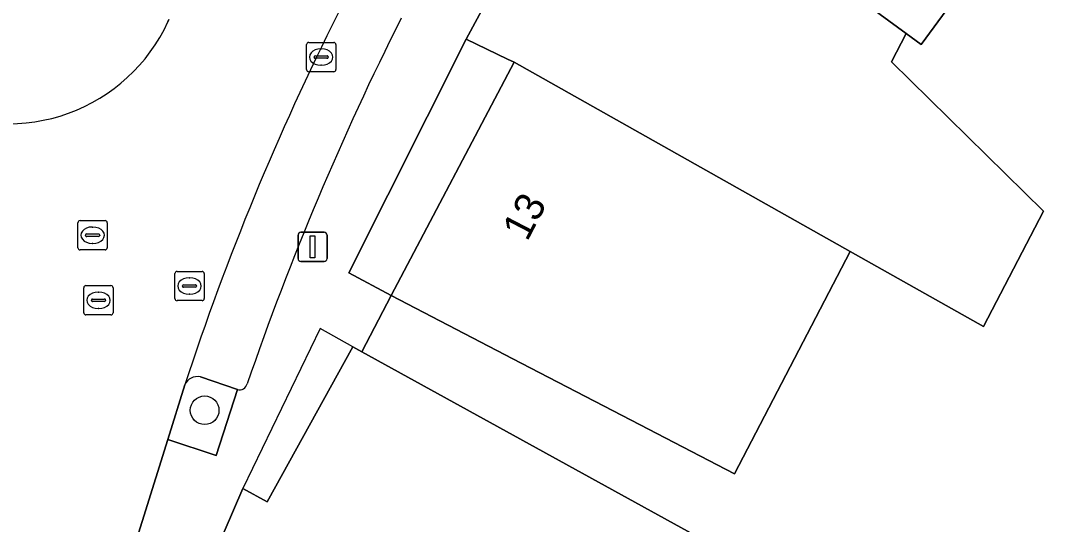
# Model space of a CAD drawing. Extents: x 159716 to 160783, y 383290 to 384031.
# Drawn here: x 160307.9 to 160343.28, y 383382.39 to 383399.58 of the extents above; entities that cross this region are included whole.
import ezdxf

# ---------------------------------------------------------------- set-up
doc = ezdxf.new("R2010")
doc.units = 0
for name, color, linetype in [('IMGEO_Boom', 7, 'Continuous'), ('IMGEO_Erf', 7, 'Continuous'), ('IMGEO_Groenvoorziening', 7, 'Continuous'), ('IMGEO_Kolk', 7, 'Continuous'), ('IMGEO_Lichtmast', 7, 'Continuous'), ('IMGEO_Pand', 7, 'Continuous'), ('IMGEO_Pand_nummerreeks', 7, 'Continuous'), ('IMGEO_Pand_overbouw', 7, 'Continuous'), ('IMGEO_Parkeervlak_open', 7, 'Continuous'), ('IMGEO_Rijbaan_lokaal_open', 7, 'Continuous'), ('IMGEO_Rioolput', 7, 'Continuous'), ('IMGEO_Voetpad_open', 7, 'Continuous')]:
    doc.layers.add(name, color=color, linetype=linetype)

msp = doc.modelspace()

# ---------------------------------------------------------------- linework, layer by layer
at = {"layer": 'IMGEO_Boom'}
msp.add_circle((160314.173, 383386.284), 0.489, dxfattribs=at)
at = {"layer": 'IMGEO_Erf'}
msp.add_lwpolyline([(160376.083, 383439.317), (160367.001, 383435.99), (160347.581, 383428.877), (160344.764, 383427.86), (160344.049, 383427.352), (160344.251, 383427.204), (160336.818, 383418.367), (160346.422, 383411.138), (160340.697, 383403.383), (160341.888, 383402.504), (160340.067, 383400.763), (160338.614, 383398.763), (160338.095, 383399.139), (160337.597, 383398.179), (160342.776, 383393.075), (160340.737, 383389.144), (160336.183, 383391.701), (160332.248, 383384.118), (160328.724, 383385.946), (160324.97, 383387.895), (160320.531, 383390.197), (160319.536, 383388.281), (160332.763, 383380.989)], dxfattribs=at)
msp.add_lwpolyline([(160324.727, 383398.163), (160324.502, 383398.272), (160323.097, 383398.955), (160319.089, 383390.972), (160320.531, 383390.197)], close=True, dxfattribs=at)
at = {"layer": 'IMGEO_Groenvoorziening'}
for points in [[(160313.497, 383387.15), (160312.912, 383385.292), (160314.565, 383384.735), (160315.29, 383386.995)], [(160315.29, 383386.995), (160314.029, 383387.421)]]:
    msp.add_lwpolyline(points, dxfattribs=at)
msp.add_arc((160313.92, 383386.977), 0.457, 76.1861, 157.8024, dxfattribs=at)
at = {"layer": 'IMGEO_Kolk'}
for p, q in [((160317.648, 383397.913), (160317.648, 383398.765)), ((160317.723, 383398.839), (160318.575, 383398.839)), ((160318.649, 383398.765), (160318.649, 383397.913)), ((160318.136, 383398.619), (160318.161, 383398.619)), ((160317.907, 383398.333), (160317.907, 383398.345)), ((160318.345, 383398.296), (160317.947, 383398.296)), ((160317.95, 383398.382), (160318.348, 383398.382)), ((160318.159, 383398.059), (160318.134, 383398.059)), ((160318.391, 383398.345), (160318.391, 383398.333)), ((160318.575, 383397.839), (160317.723, 383397.839))]:
    msp.add_line(p, q, dxfattribs=at)
for points in [[(160317.648, 383397.913), (160317.648, 383398.765)], [(160317.723, 383398.839), (160318.575, 383398.839)], [(160318.649, 383398.765), (160318.649, 383397.913)], [(160318.575, 383397.839), (160317.723, 383397.839)]]:
    msp.add_lwpolyline(points, dxfattribs=at)
for centre, radius, start, end in [((160317.725, 383398.763), 0.0765, 91.552, 178.448), ((160317.725, 383398.763), 0.0765, 91.552, 178.448), ((160318.573, 383398.763), 0.0765, 1.552, 88.448), ((160318.573, 383398.763), 0.0765, 1.552, 88.448), ((160317.947, 383398.342), 0.0403, 85.8775, 175.7526), ((160317.944, 383398.332), 0.0366, 178.938, 274.7102), ((160318.348, 383398.339), 0.043, 264.8664, 352.4533), ((160318.352, 383398.344), 0.0386, 1.7309, 96.639), ((160317.725, 383397.915), 0.0765, 181.552, 268.448), ((160317.725, 383397.915), 0.0765, 181.552, 268.448), ((160318.573, 383397.915), 0.0765, 271.552, 358.448), ((160318.573, 383397.915), 0.0765, 271.552, 358.448)]:
    msp.add_arc(centre, radius, start, end, dxfattribs=at)
for centre, major_axis, ratio, start_param, end_param in [((160318.135, 383398.339), (-0.387, 0.002), 0.722429, 4.712389, 7.853982), ((160318.16, 383398.339), (-0.39, 0.002), 0.717154, 1.570796, 4.712389)]:
    msp.add_ellipse(centre, major_axis=major_axis, ratio=ratio, start_param=start_param, end_param=end_param, dxfattribs=at)
at = {"layer": 'IMGEO_Lichtmast'}
for p, q in [((160317.357, 383391.461), (160317.357, 383392.261)), ((160317.357, 383392.261), (160317.357, 383391.461)), ((160317.457, 383392.361), (160318.247, 383392.361)), ((160318.247, 383392.361), (160317.457, 383392.361)), ((160318.347, 383392.261), (160318.347, 383391.461)), ((160318.347, 383391.461), (160318.347, 383392.261)), ((160318.247, 383391.361), (160317.457, 383391.361)), ((160317.457, 383391.361), (160318.247, 383391.361))]:
    msp.add_line(p, q, dxfattribs=at)
msp.add_lwpolyline([(160317.777, 383392.236), (160317.927, 383392.236), (160317.927, 383391.486), (160317.777, 383391.486), (160317.777, 383392.236)], dxfattribs=at)
for centre, start, end in [((160317.457, 383392.261), 90, 180), ((160317.457, 383392.261), 90, 180), ((160318.247, 383392.261), 0, 90), ((160318.247, 383392.261), 360, 90), ((160317.457, 383391.461), 180, 270), ((160317.457, 383391.461), 180, 270), ((160318.247, 383391.461), 270, 0), ((160318.247, 383391.461), 270, 0)]:
    msp.add_arc(centre, 0.1, start, end, dxfattribs=at)
at = {"layer": 'IMGEO_Pand'}
for points in [[(160346.422, 383411.138), (160336.818, 383418.367), (160336.495, 383418.61), (160327.755, 383406.719), (160338.095, 383399.139), (160338.614, 383398.763), (160340.067, 383400.763), (160341.888, 383402.504), (160340.697, 383403.383)], [(160337.597, 383398.179), (160338.095, 383399.139), (160327.755, 383406.719), (160327.556, 383406.448), (160327.951, 383406.158), (160326.397, 383404.048), (160325.966, 383404.28), (160323.097, 383398.955), (160324.502, 383398.272), (160324.727, 383398.163), (160336.183, 383391.701), (160340.737, 383389.144), (160342.776, 383393.075)], [(160336.183, 383391.701), (160324.727, 383398.163), (160320.531, 383390.197), (160324.97, 383387.895), (160328.724, 383385.946), (160332.248, 383384.118)], [(160319.536, 383388.281), (160319.229, 383388.45), (160316.304, 383383.157), (160315.48, 383383.61), (160311.554, 383374.506), (160311.589, 383373.702), (160314.742, 383371.969), (160312.038, 383367.09), (160312.191, 383364.819), (160320.956, 383359.966), (160323.258, 383367.115), (160328.865, 383370.206), (160331.054, 383372.22), (160330.864, 383372.324), (160328.643, 383373.555), (160332.763, 383380.989)]]:
    msp.add_lwpolyline(points, close=True, dxfattribs=at)
at = {"layer": 'IMGEO_Pand_overbouw'}
msp.add_lwpolyline([(160319.229, 383388.45), (160318.108, 383389.071), (160315.48, 383383.61), (160316.304, 383383.157)], close=True, dxfattribs=at)
at = {"layer": 'IMGEO_Parkeervlak_open'}
msp.add_lwpolyline([(160314.029, 383387.421), (160315.29, 383386.995)], dxfattribs=at)
for centre, radius, start, end in [((160400.482, 383358.736), 91.508, 153.31144, 161.91012), ((160410.195, 383354.715), 99.991, 153.28158, 161.04988), ((160313.92, 383386.977), 0.457, 76.1861, 157.8024), ((160315.366, 383387.247), 0.263, 253.1284, 346.8051)]:
    msp.add_arc(centre, radius, start, end, dxfattribs=at)
at = {"layer": 'IMGEO_Rijbaan_lokaal_open'}
for points in [[(160312.955, 383399.617), (160312.922, 383399.536)], [(160310.416, 383377.156), (160311.627, 383381.183), (160312.912, 383385.292), (160313.497, 383387.15)]]:
    msp.add_lwpolyline(points, dxfattribs=at)
for centre, radius, start, end in [((160400.482, 383358.736), 91.508, 153.31144, 161.91012), ((160307.473, 383402.067), 6.008, 244.9277, 335.0857)]:
    msp.add_arc(centre, radius, start, end, dxfattribs=at)
at = {"layer": 'IMGEO_Rioolput'}
for p, q in [((160309.926, 383392.758), (160310.778, 383392.758)), ((160309.851, 383391.832), (160309.851, 383392.684)), ((160310.339, 383392.538), (160310.364, 383392.538)), ((160310.852, 383392.684), (160310.852, 383391.832)), ((160310.11, 383392.252), (160310.11, 383392.264)), ((160310.548, 383392.215), (160310.15, 383392.215)), ((160310.153, 383392.301), (160310.551, 383392.301)), ((160310.594, 383392.264), (160310.594, 383392.252)), ((160310.778, 383391.758), (160309.926, 383391.758)), ((160310.362, 383391.978), (160310.337, 383391.978)), ((160313.231, 383391.025), (160314.083, 383391.025)), ((160313.156, 383390.099), (160313.156, 383390.951)), ((160313.644, 383390.805), (160313.669, 383390.805)), ((160314.157, 383390.951), (160314.157, 383390.099)), ((160310.051, 383389.612), (160310.051, 383390.464)), ((160310.126, 383390.538), (160310.978, 383390.538)), ((160310.539, 383390.318), (160310.564, 383390.318)), ((160311.052, 383390.464), (160311.052, 383389.612)), ((160313.415, 383390.519), (160313.415, 383390.531)), ((160313.853, 383390.482), (160313.455, 383390.482)), ((160313.458, 383390.568), (160313.856, 383390.568)), ((160313.899, 383390.531), (160313.899, 383390.519)), ((160310.31, 383390.032), (160310.31, 383390.044)), ((160310.748, 383389.995), (160310.35, 383389.995)), ((160310.353, 383390.081), (160310.751, 383390.081)), ((160310.794, 383390.044), (160310.794, 383390.032)), ((160314.083, 383390.025), (160313.231, 383390.025)), ((160313.667, 383390.245), (160313.642, 383390.245)), ((160310.562, 383389.758), (160310.537, 383389.758)), ((160310.978, 383389.538), (160310.126, 383389.538))]:
    msp.add_line(p, q, dxfattribs=at)
for points in [[(160309.926, 383392.758), (160310.778, 383392.758)], [(160309.851, 383391.832), (160309.851, 383392.684)], [(160310.852, 383392.684), (160310.852, 383391.832)], [(160310.778, 383391.758), (160309.926, 383391.758)], [(160313.231, 383391.025), (160314.083, 383391.025)], [(160313.156, 383390.099), (160313.156, 383390.951)], [(160314.157, 383390.951), (160314.157, 383390.099)], [(160310.051, 383389.612), (160310.051, 383390.464)], [(160310.126, 383390.538), (160310.978, 383390.538)], [(160311.052, 383390.464), (160311.052, 383389.612)], [(160314.083, 383390.025), (160313.231, 383390.025)], [(160310.978, 383389.538), (160310.126, 383389.538)]]:
    msp.add_lwpolyline(points, dxfattribs=at)
for centre, radius, start, end in [((160309.928, 383392.682), 0.0765, 91.552, 178.448), ((160309.928, 383392.682), 0.0765, 91.552, 178.448), ((160310.776, 383392.682), 0.0765, 1.552, 88.448), ((160310.776, 383392.682), 0.0765, 1.552, 88.448), ((160310.15, 383392.261), 0.0403, 85.8775, 175.7526), ((160310.147, 383392.251), 0.0366, 178.938, 274.7102), ((160310.551, 383392.258), 0.043, 264.8664, 352.4533), ((160310.555, 383392.263), 0.0386, 1.7309, 96.639), ((160309.928, 383391.834), 0.0765, 181.552, 268.448), ((160309.928, 383391.834), 0.0765, 181.552, 268.448), ((160310.776, 383391.834), 0.0765, 271.552, 358.448), ((160310.776, 383391.834), 0.0765, 271.552, 358.448), ((160313.233, 383390.949), 0.0765, 91.552, 178.448), ((160313.233, 383390.949), 0.0765, 91.552, 178.448), ((160314.081, 383390.949), 0.0765, 1.552, 88.448), ((160314.081, 383390.949), 0.0765, 1.552, 88.448), ((160310.128, 383390.462), 0.0765, 91.552, 178.448), ((160310.128, 383390.462), 0.0765, 91.552, 178.448), ((160310.976, 383390.462), 0.0765, 1.552, 88.448), ((160310.976, 383390.462), 0.0765, 1.552, 88.448), ((160313.455, 383390.528), 0.0403, 85.8775, 175.7526), ((160313.452, 383390.518), 0.0366, 178.938, 274.7102), ((160313.856, 383390.525), 0.043, 264.8664, 352.4533), ((160313.86, 383390.53), 0.0386, 1.7309, 96.639), ((160310.35, 383390.041), 0.0403, 85.8775, 175.7526), ((160310.347, 383390.031), 0.0366, 178.938, 274.7102), ((160310.751, 383390.038), 0.043, 264.8664, 352.4533), ((160310.755, 383390.043), 0.0386, 1.7309, 96.639), ((160313.233, 383390.101), 0.0765, 181.552, 268.448), ((160313.233, 383390.101), 0.0765, 181.552, 268.448), ((160314.081, 383390.101), 0.0765, 271.552, 358.448), ((160314.081, 383390.101), 0.0765, 271.552, 358.448), ((160310.128, 383389.614), 0.0765, 181.552, 268.448), ((160310.128, 383389.614), 0.0765, 181.552, 268.448), ((160310.976, 383389.614), 0.0765, 271.552, 358.448), ((160310.976, 383389.614), 0.0765, 271.552, 358.448)]:
    msp.add_arc(centre, radius, start, end, dxfattribs=at)
for centre, major_axis, ratio, start_param, end_param in [((160310.338, 383392.258), (-0.387, 0.002), 0.722429, 4.712389, 7.853982), ((160310.363, 383392.258), (-0.39, 0.002), 0.717154, 1.570796, 4.712389), ((160313.643, 383390.525), (-0.387, 0.002), 0.722429, 4.712389, 7.853982), ((160313.668, 383390.525), (-0.39, 0.002), 0.717154, 1.570796, 4.712389), ((160310.538, 383390.038), (-0.387, 0.002), 0.722429, 4.712389, 7.853982), ((160310.563, 383390.038), (-0.39, 0.002), 0.717154, 1.570796, 4.712389)]:
    msp.add_ellipse(centre, major_axis=major_axis, ratio=ratio, start_param=start_param, end_param=end_param, dxfattribs=at)
at = {"layer": 'IMGEO_Voetpad_open'}
for points in [[(160311.554, 383374.506), (160315.48, 383383.61), (160316.304, 383383.157), (160319.229, 383388.45), (160319.536, 383388.281), (160320.531, 383390.197), (160319.089, 383390.972), (160323.097, 383398.955), (160325.966, 383404.28), (160326.397, 383404.048), (160327.951, 383406.158), (160327.556, 383406.448), (160327.755, 383406.719), (160336.495, 383418.61), (160336.818, 383418.367), (160344.251, 383427.204), (160344.049, 383427.352), (160344.764, 383427.86), (160347.581, 383428.877), (160367.001, 383435.99), (160376.083, 383439.317)], [(160312.922, 383399.536), (160312.955, 383399.617)], [(160315.29, 383386.995), (160314.565, 383384.735), (160312.912, 383385.292), (160311.627, 383381.183), (160310.416, 383377.156)]]:
    msp.add_lwpolyline(points, dxfattribs=at)
for centre, radius, start, end in [((160307.473, 383402.067), 6.008, 244.9277, 335.0857), ((160410.195, 383354.715), 99.991, 153.28158, 161.04988), ((160315.366, 383387.247), 0.263, 253.1284, 346.8051)]:
    msp.add_arc(centre, radius, start, end, dxfattribs=at)

# ---------------------------------------------------------------- texts
at = {"layer": 'IMGEO_Pand_nummerreeks'}
msp.add_text('13', height=1, rotation=62.567, dxfattribs=at).set_placement((160325.172, 383392.017))

doc.saveas('drawing.dxf')
